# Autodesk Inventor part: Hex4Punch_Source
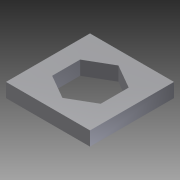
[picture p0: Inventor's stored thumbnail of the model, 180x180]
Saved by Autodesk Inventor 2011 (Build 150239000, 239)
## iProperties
Created: 2007-02
Part Number: Hex4Punch_Source
Material: Default
Document SubType Name: Sheet Metal
Designer: Autodesk, Inc.
Mass: 0.0256077 g
Surface Area: 0.872154 cm^2
Volume: 0.0256077 cm^3
Density: 1 g/cm^3
Sheet Metal Rule: 1 mm
Author: Autodesk, Inc.
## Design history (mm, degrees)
node "Face1"
  sketch "Sketch1"
    geometry: L1 (-3, 3)-(3, 3); L2 (3, 3)-(3, -3); L3 (3, -3)-(-3, -3); L4 (-3, -3)-(-3, 3); L5 (-3, 3)-(3, -3); 2 further points
    constraints: 10 end point, 2 parallel, 1 coincident, 1 horizontal, 1 midpoint, 1 perpendicular
    dimensions: "d0" = 6 distance of L1.start L1.end; "d1" = 6 distance of L3.end L1.start (= d0)
sketch "Sketch2"
  geometry: L1 (1.732, 1.03)-(1.732, -0.97); L2 (1.732, -0.97)-(0, -1.97); L3 (0, -1.97)-(-1.732, -0.97); L4 (-1.732, -0.97)-(-1.732, 1.03); L5 (-1.732, 1.03)-(0, 2.03); L6 (0, 2.03)-(1.732, 1.03); 2 further points
  constraints: 12 end point, 1 coincident, 1 vertical, 13 other
  dimensions: "d3" = 4 distance of L2.end L5.end
cut "Cut1" sketch "Sketch2" dims "d4" = 1 (= Thickness), "d5" = 0
body "Solid1"
face "Plate1" dims "Thickness" = 1
other parameters: "BendRadius" = 0.5, "BendReliefWidth" = 1 (= Thickness), "BendReliefDepth" = 0.5 (= 0.5 x Thickness), "CornerReliefSize" = 4 (= 4 x Thickness), "SeamGap" = 0.01, "MinimumRemnant" = 2 (= 2 x Thickness), "TransitionRadius" = 0.5 (= BendRadius), "JacobiRadiusSize" = 1 (= Thickness), "d2" = 0.5 (= BendRadius), "GapSize" = 1 (= Thickness)
